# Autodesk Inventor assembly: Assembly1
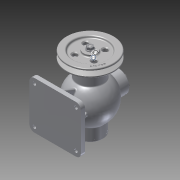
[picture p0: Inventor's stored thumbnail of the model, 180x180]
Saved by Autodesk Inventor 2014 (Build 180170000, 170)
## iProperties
Created: 2017-01
Part Number: Assembly1
Document SubType Name: Assembly
Designer: ksu
Author: ksu
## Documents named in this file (19)
- C:\Users\ksu\Desktop\470118V1012\Assembly1.iam
- C:\Users\ksu\Desktop\470118V1012\멈춤링- 15 x 1.ipt
- C:\Users\ksu\Desktop\470118V1012\멈춤링- 35x1.6.ipt
- KS B 1336 - 35x1.6.ipt
- C:\Users\ksu\Desktop\470118V1012\베어링- 6202.ipt
- KS B 2023 - 6202 - 15 x 35 x 11 - 7.8.ipt
- C:\Users\ksu\Desktop\470118V1012\본체.ipt
- C:\Users\ksu\Desktop\470118V1012\볼트 M4 x 12.ipt
- C:\Users\ksu\Desktop\470118V1012\볼트 M4 x 16.ipt
- C:\Users\ksu\Desktop\470118V1012\부시.ipt
- C:\Users\ksu\Desktop\470118V1012\상부커버.ipt
- C:\Users\ksu\Desktop\470118V1012\슬라이드.ipt
- C:\Users\ksu\Desktop\470118V1012\앞커버.ipt
- C:\Users\ksu\Desktop\470118V1012\오일실 15 30 7.ipt
- C:\Users\ksu\Desktop\470118V1012\키 4 x 4 x 12.ipt
- C:\Users\ksu\Desktop\470118V1012\편심축.ipt
- C:\Users\ksu\Desktop\470118V1012\V-벨트풀리.ipt
- C:\Users\ksu\Desktop\470118V1012\너트 M8.ipt
- C:\Users\ksu\Desktop\470118V1012\뒤커버.ipt
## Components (16 placed, 5 different names)
1. KS B 1336 - 35x1.6:1 — Mate:63
2. KS B 2023 - 6202 - 15 x 35 x 11 - 7.8:1 — Mate:47, Mate:48, Mate:65, Mate:66, Mate:67
3. KS B 1021 - 에 따름 ISO 1207 - 미터 A  M 4 x 12:1 — Mate:25, Mate:44
4. ISO 4762 M4 x 16:1 — Mate:4, Mate:8
5. V-벨트풀리:1 — Mate:35, Mate:36
6. ISO 4762 M4 x 16:2 — Mate:11, Mate:12
7. ISO 4762 M4 x 16:3 — Mate:7, Mate:10
8. ISO 4762 M4 x 16:4 — Mate:6, Mate:9
9. ISO 4762 M4 x 16:5 — Mate:57, Mate:62
10. ISO 4762 M4 x 16:6 — Mate:58, Mate:61
11. ISO 4762 M4 x 16:7 — Mate:55, Mate:59
12. ISO 4762 M4 x 16:8 — Mate:56, Mate:60
13. KS B 1021 - 에 따름 ISO 1207 - 미터 A  M 4 x 12:2 — Mate:27, Mate:43
14. KS B 1021 - 에 따름 ISO 1207 - 미터 A  M 4 x 12:3 — Mate:26, Mate:45
15. KS B 1021 - 에 따름 ISO 1207 - 미터 A  M 4 x 12:4 — Mate:28, Mate:46
16. KS B 2023 - 6202 - 15 x 35 x 11 - 7.8:2 — Mate:63
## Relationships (32: Mate 32)
- Mate:4: ISO 4762 M4 x 16:1
- Mate:6: ISO 4762 M4 x 16:4
- Mate:7: ISO 4762 M4 x 16:3
- Mate:8: ISO 4762 M4 x 16:1
- Mate:9: ISO 4762 M4 x 16:4
- Mate:10: ISO 4762 M4 x 16:3
- Mate:11: ISO 4762 M4 x 16:2
- Mate:12: ISO 4762 M4 x 16:2
- Mate:25: KS B 1021 - 에 따름 ISO 1207 - 미터 A  M 4 x 12:1
- Mate:26: KS B 1021 - 에 따름 ISO 1207 - 미터 A  M 4 x 12:3
- Mate:27: KS B 1021 - 에 따름 ISO 1207 - 미터 A  M 4 x 12:2
- Mate:28: KS B 1021 - 에 따름 ISO 1207 - 미터 A  M 4 x 12:4
- Mate:35: V-벨트풀리:1
- Mate:36: V-벨트풀리:1
- Mate:43: KS B 1021 - 에 따름 ISO 1207 - 미터 A  M 4 x 12:2
- Mate:44: KS B 1021 - 에 따름 ISO 1207 - 미터 A  M 4 x 12:1
- Mate:45: KS B 1021 - 에 따름 ISO 1207 - 미터 A  M 4 x 12:3
- Mate:46: KS B 1021 - 에 따름 ISO 1207 - 미터 A  M 4 x 12:4
- Mate:47: KS B 2023 - 6202 - 15 x 35 x 11 - 7.8:1
- Mate:48: KS B 2023 - 6202 - 15 x 35 x 11 - 7.8:1
- Mate:55: ISO 4762 M4 x 16:7
- Mate:56: ISO 4762 M4 x 16:8
- Mate:57: ISO 4762 M4 x 16:5
- Mate:58: ISO 4762 M4 x 16:6
- Mate:59: ISO 4762 M4 x 16:7
- Mate:60: ISO 4762 M4 x 16:8
- Mate:61: ISO 4762 M4 x 16:6
- Mate:62: ISO 4762 M4 x 16:5
- Mate:63: KS B 1336 - 35x1.6:1 ↔ KS B 2023 - 6202 - 15 x 35 x 11 - 7.8:2
- Mate:65: KS B 2023 - 6202 - 15 x 35 x 11 - 7.8:1
- Mate:66: KS B 2023 - 6202 - 15 x 35 x 11 - 7.8:1
- Mate:67: KS B 2023 - 6202 - 15 x 35 x 11 - 7.8:1
